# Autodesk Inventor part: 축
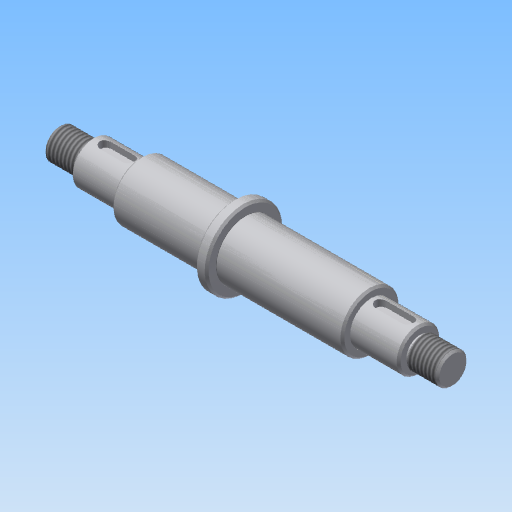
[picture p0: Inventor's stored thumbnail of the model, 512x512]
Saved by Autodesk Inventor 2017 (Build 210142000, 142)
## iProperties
Created: 2021-06
Part Number: 축
Material: 강철, 연강
Document SubType Name: Modeling
Designer: mdu
Density: 1 g/cm^3
Appearance: 흰색
CustomPartVersion: 1
Author: mdu
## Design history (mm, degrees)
sketch "주 스케치"
  geometry: L1 (0, 0)-(203, 0) reference; L2 (0, 0)-(0, 8); L3 (0, 8)-(17, 8); L4 (17, 8)-(17, 11); L5 (17, 11)-(42, 11); L6 (42, 11)-(42, 15); L7 (42, 15)-(90, 15); L8 (90, 15)-(90, 20); L9 (96, 20)-(96, 15); L10 (90, 20)-(96, 20); L11 (161, 15)-(161, 11); L12 (96, 15)-(161, 15); L13 (186, 11)-(186, 8); L14 (161, 11)-(186, 11); L15 (203, 8)-(203, 0); L16 (186, 8)-(203, 8)
  constraints: 32 end point, 9 horizontal, 8 vertical
  dimensions: "d3" = 16 diameter of L3 L1 (derived); "d4" = 22 diameter of L5 L1 (derived); "d5" = 30 diameter of L7 L1 (derived); "d6" = 40 diameter of L10 L1 (derived); "d7" = 30 diameter of L12 L1 (derived); "d8" = 22 diameter of L14 L1 (derived); "d9" = 16 diameter of L16 L1 (derived)
revolve "회전1" sketch "주 스케치" stored, may be unused: angle "d10" = 0 deg
chamfer "모따기1" distance "d11" = 1; stored, may be unused: second distance "d12" = 1, angle "d13" = 45 deg
chamfer "모따기2" distance "d14" = 1; stored, may be unused: second distance "d15" = 1, angle "d16" = 45 deg
node "키홈1"
chamfer "모따기3" distance "d17" = 1; stored, may be unused: second distance "d18" = 1, angle "d19" = 45 deg
fillet "모깎기1" dims "d20" = 0.3
chamfer "모따기4" distance "d21" = 1; stored, may be unused: second distance "d22" = 1, angle "d23" = 45 deg
chamfer "모따기5" distance "d24" = 1; stored, may be unused: second distance "d25" = 1, angle "d26" = 45 deg
fillet "모깎기2" dims "d27" = 0.3
chamfer "모따기6" distance "d28" = 1; stored, may be unused: second distance "d29" = 1, angle "d30" = 45 deg
chamfer "모따기7" distance "d31" = 1; stored, may be unused: second distance "d32" = 1, angle "d33" = 45 deg
node "키홈2"
chamfer "모따기8" distance "d34" = 1; stored, may be unused: second distance "d35" = 1, angle "d36" = 45 deg
sketch "스케치3"
  geometry: L1 (1, 8)-(17, 8) reference; L2 (17, -10)-(17, 10) reference; L3 (186, 10)-(186, -10) reference; L4 (186, 8)-(202, 8) reference; L5 (203, 7)-(203, -7) reference; L6 (0, 0)-(203, 0); L7 (17, 8)-(15.5, 8); L8 (15.5, 8)-(15.5, 7); L9 (15.5, 7)-(17, 7); L10 (17, 7)-(17, 8); L11 (186, 8)-(187.5, 8); L12 (187.5, 8)-(187.5, 7); L13 (187.5, 7)-(186, 7); L14 (186, 7)-(186, 8)
  constraints: 18 end point, 4 parallel, 2 horizontal, 2 perpendicular, 1 midpoint
  dimensions: "d37" = 14 diameter of L13 L6; "d39" = 1.5 distance of L12.end L13.end; "d40" = 14 diameter of L9 L6; "d41" = 1.5 distance of L8.end L9.end
revolve "회전2" sketch "스케치3" stored, may be unused: angle "d42" = 90 deg
feature "스레드1" dims "d43" = 10, "d44" = 0
feature "스레드2" dims "d45" = 10, "d46" = 0
sketch "스케치4"
  geometry: L1 (186, 7)-(186, -7) reference; L2 (186, 10)-(186, -10) reference; L3 (161, -11)-(185, -11) reference; L4 (165.225, -11)-(165.225, -9); L5 (165.225, -9)-(167.225, -11); L6 (165.225, -11)-(167.225, -11); 1 further point
  constraints: 6 end point, 2 point on line, 1 collinear, 1 perpendicular
  dimensions: "d47" = 20.77468 distance from line of L2 L4.start; "d48" = 4 diameter of L5.end L4; "d49" = 45 deg angle of L4 L5
revolve "회전3" sketch "스케치4" stored, may be unused: angle "d50" = 90 deg
node "솔리드1"
feature "iFeature3:1"
feature "iFeature3:2"
node "투영된 루프1"
other parameters: "d0" = 0, "d1" = 0, "d2" = 0
